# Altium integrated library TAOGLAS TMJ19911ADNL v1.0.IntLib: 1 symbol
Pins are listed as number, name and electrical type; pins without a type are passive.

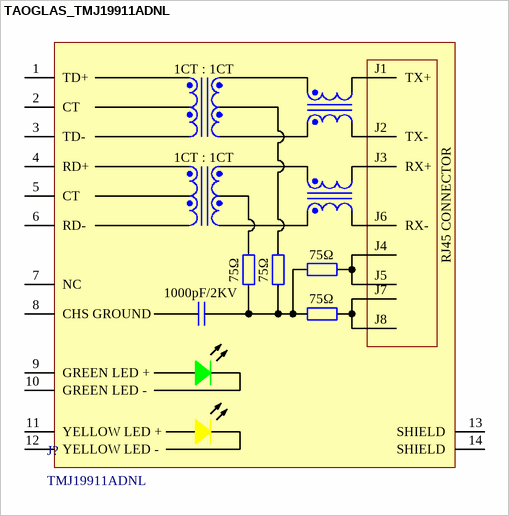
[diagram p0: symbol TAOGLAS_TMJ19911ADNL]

## TAOGLAS_TMJ19911ADNL
designator J?, comment TMJ19911ADNL
RJ45 connector with integrated magnetics 10/100 Base-T Single Port Tab-UP with right angle SMT mount and LEDs; ComponentLibStatus: Created; MFG: Taoglas; Temp_High: +85C; Temp_Low: -40C
footprint TAOGLAS_TMJ19911ADNL (RJ45 connector with integrated magnetics 10/100 Base-T Single Port Tab-UP with right angle SMT mount and LEDs)
pins: 1 TD+, 2 CT, 3 TD-, 4 RD+, 5 CT, 6 RD-, 7 NC, 8 CHS GROUND, 9 GREEN LED +, 10 GREEN LED -, 11 YELLOW LED +, 12 YELLOW LED -, 13 SHIELD, 14 SHIELD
